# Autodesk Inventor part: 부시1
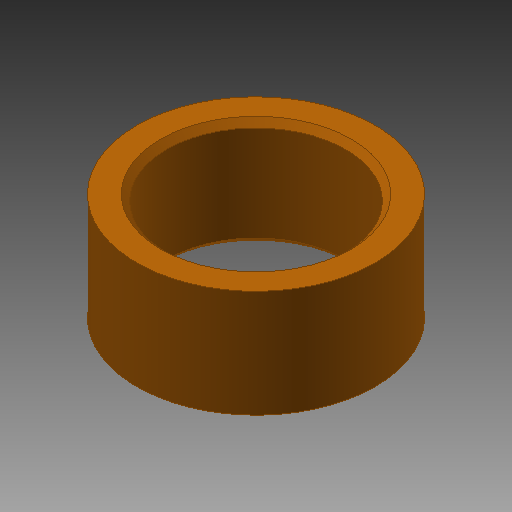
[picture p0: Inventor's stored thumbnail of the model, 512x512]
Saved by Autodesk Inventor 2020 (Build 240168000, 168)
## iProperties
Created: 2016-08
Part Number: 부시1
Material: 강철, 탄소
Document SubType Name: Modeling
Designer: mduedu
Density: 7.87 g/cm^3
Appearance: 주황색
Author: mduedu
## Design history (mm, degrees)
sketch "스케치1"
  geometry: C1 r 7.5 at (0, 0); C2 r 10 at (0, 0); 1 further point
  constraints: 2 centre point, 2 coincident
  dimensions: "d0" = 15 diameter of C1; "d1" = 20 diameter of C2
extrude "돌출1" new body sketch "스케치1" stored distance "d2" = 9; taper "d3" = 0 deg
chamfer "모따기1" distance "d4" = 0.5; stored, may be unused: second distance "d5" = 2, angle "d6" = 45 deg
node "솔리드1"
